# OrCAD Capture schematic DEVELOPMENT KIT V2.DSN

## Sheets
1 Diagrama de Bloques: size A4; title: Development Kit V1; Diagrama de Bloques; rev: 2.0; company: Oficina Técnica, UC3M; note: OT-2015-2706
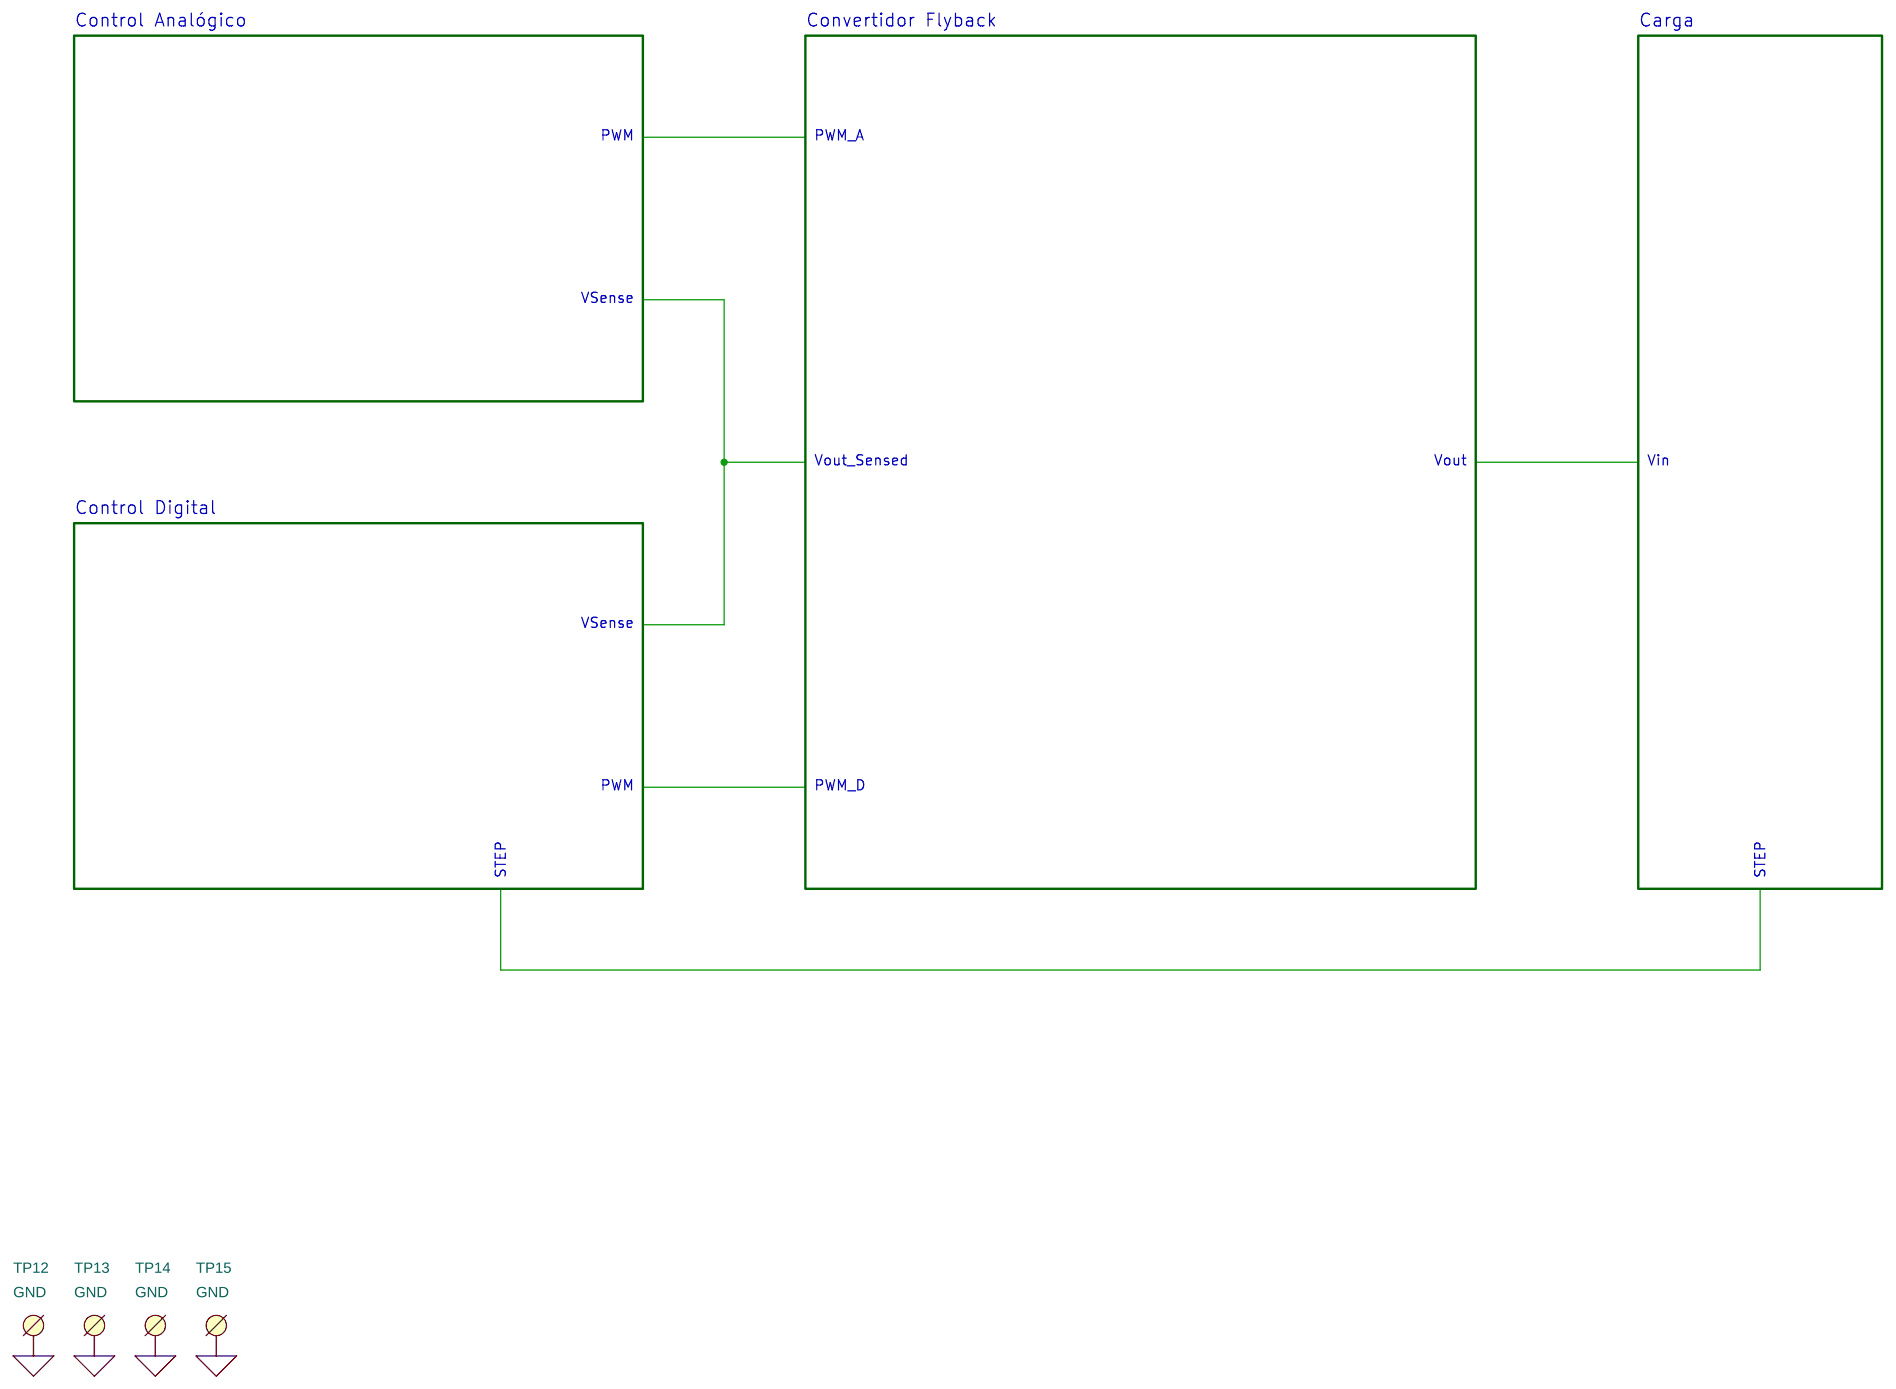
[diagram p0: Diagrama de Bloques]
2 Control Analógico: size A4; title: Development Kit V1; Control Analógico; block Control Analógico
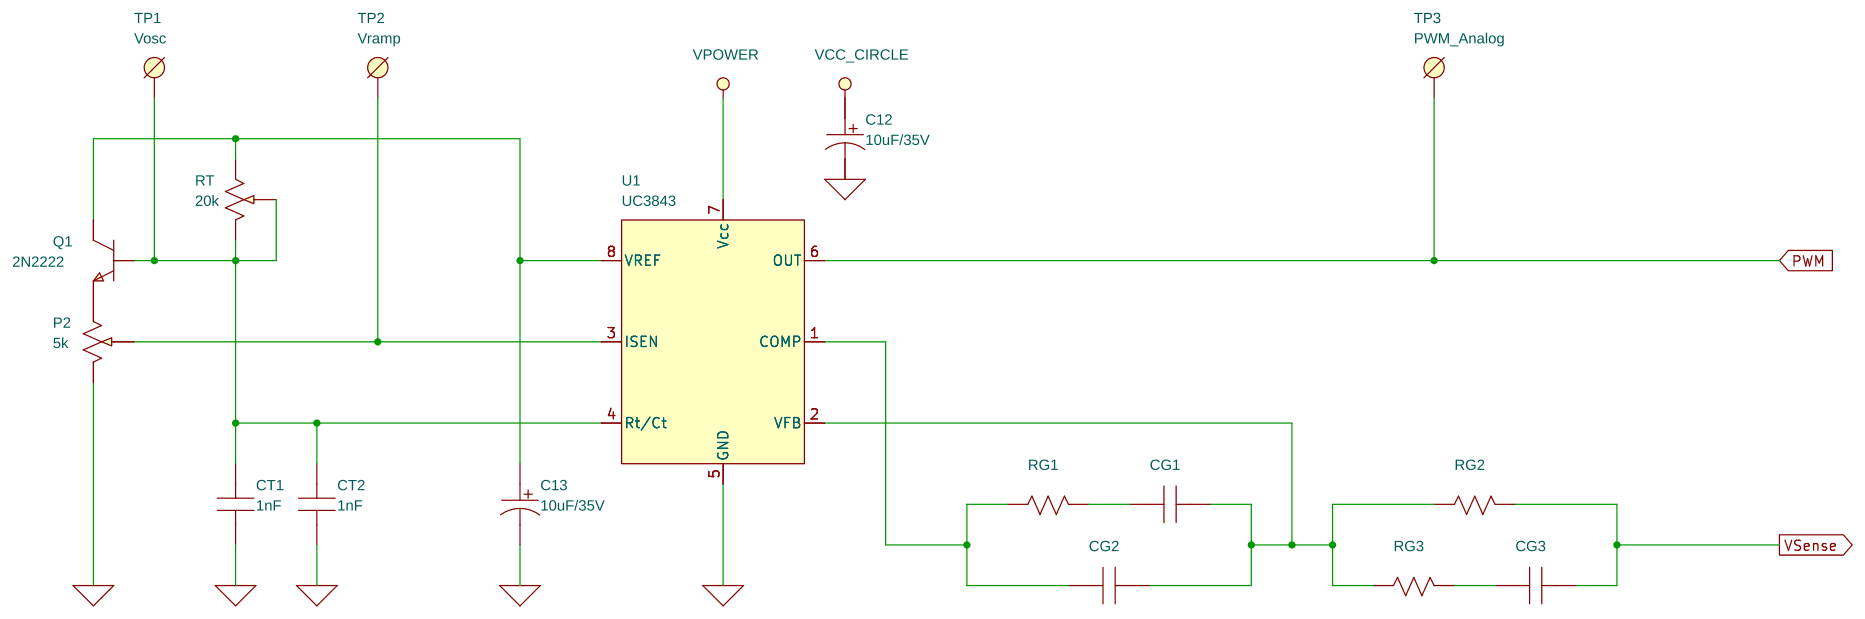
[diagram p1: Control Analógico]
3 Control Digital: size A4; title: Development Kit V1; Control Digital; block Control Digital
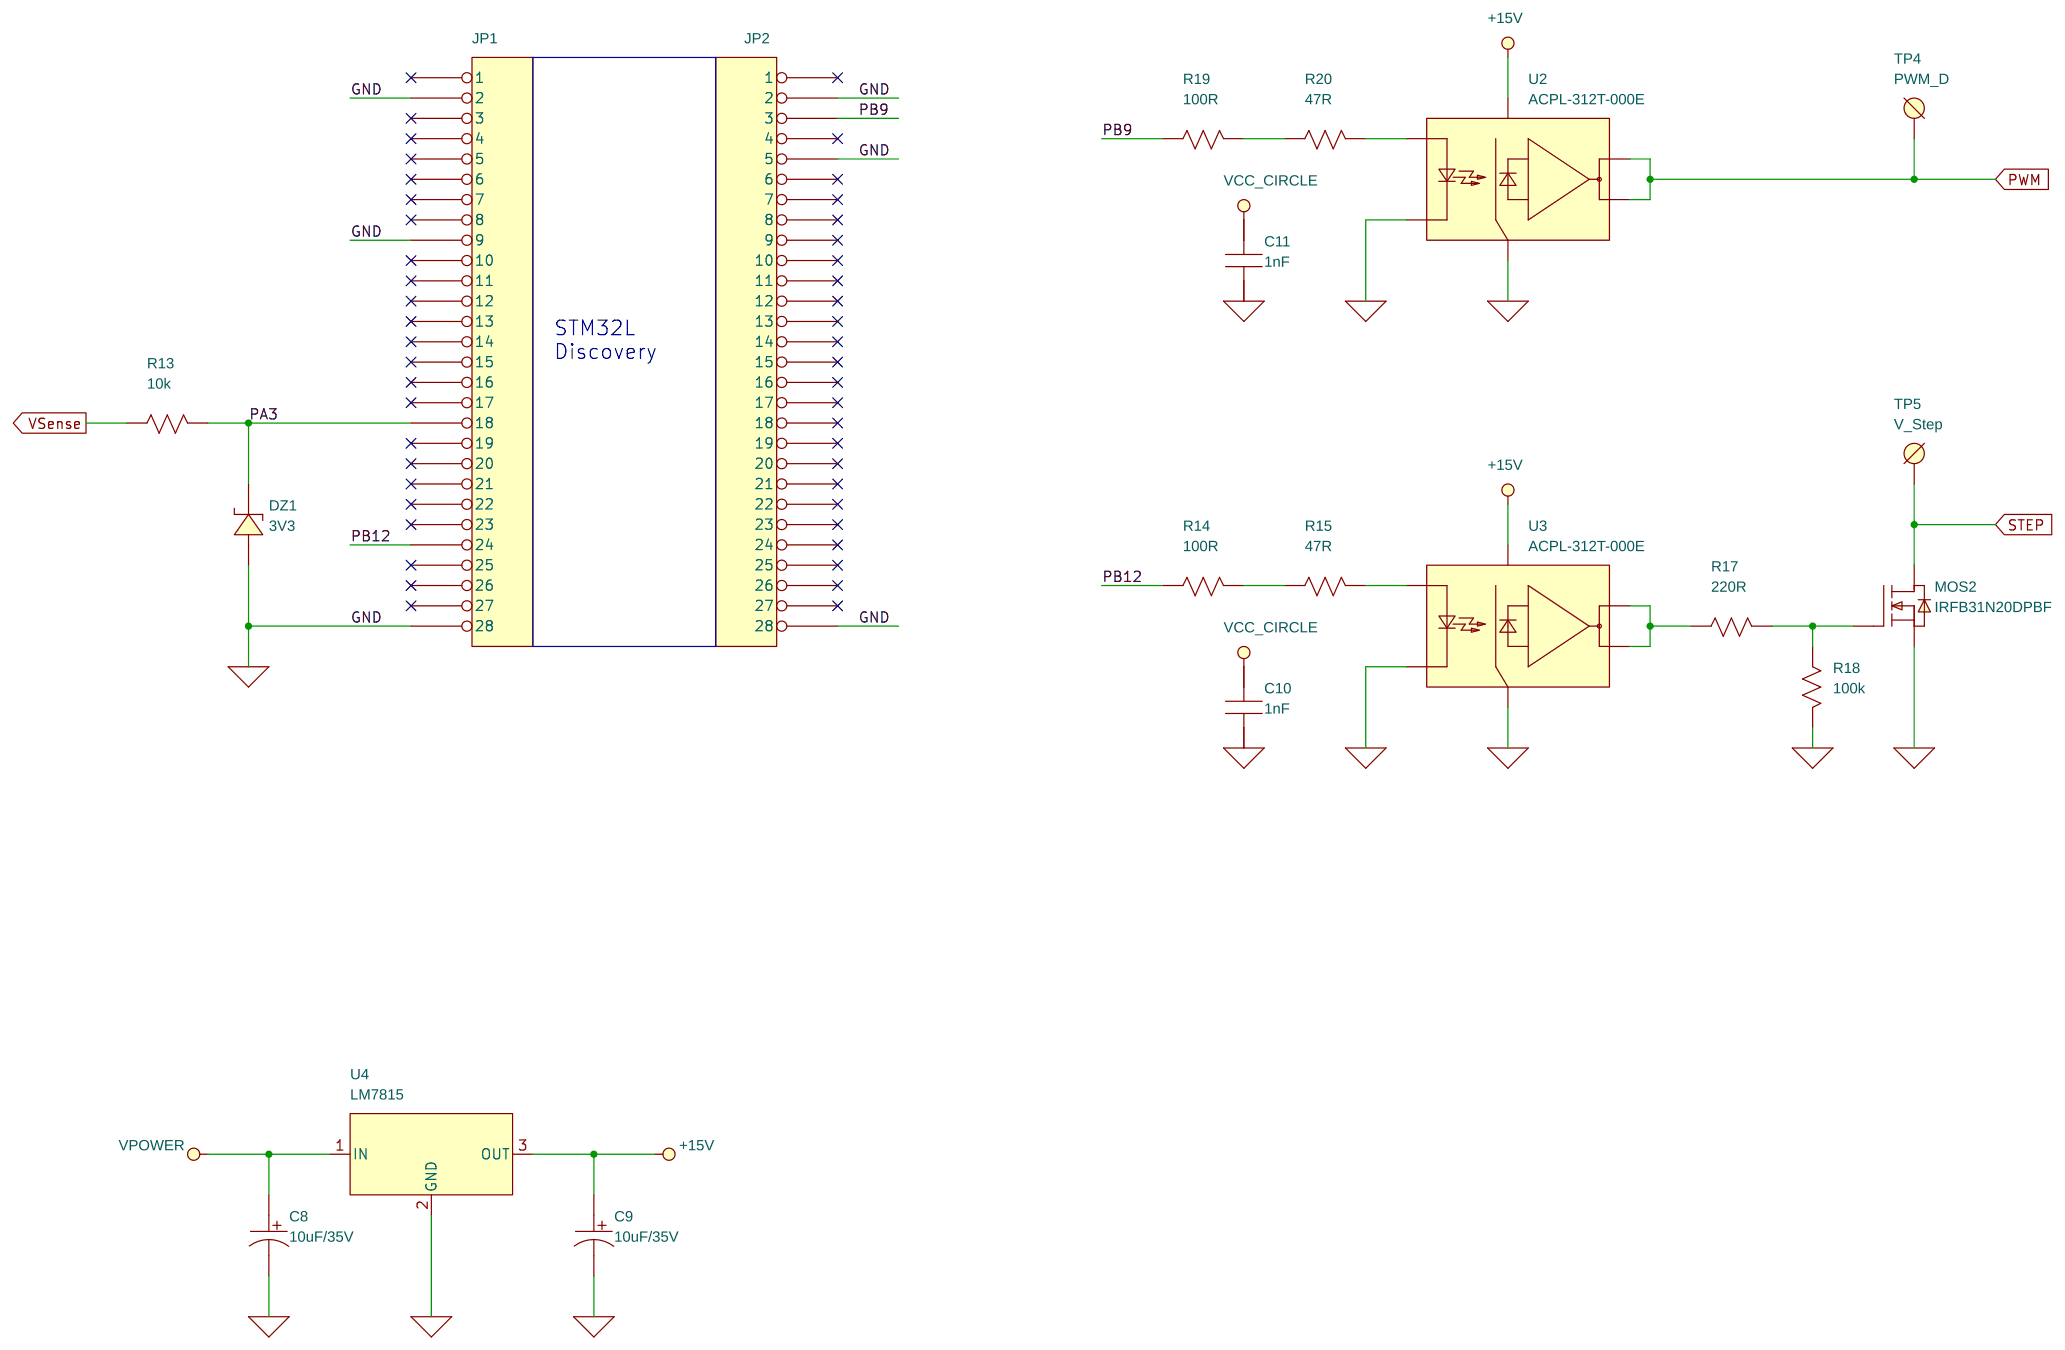
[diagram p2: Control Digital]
4 Convertidor Flyback: size A4; title: Development Kit V1; Convertidor Flyback; block Convertidor Flyback
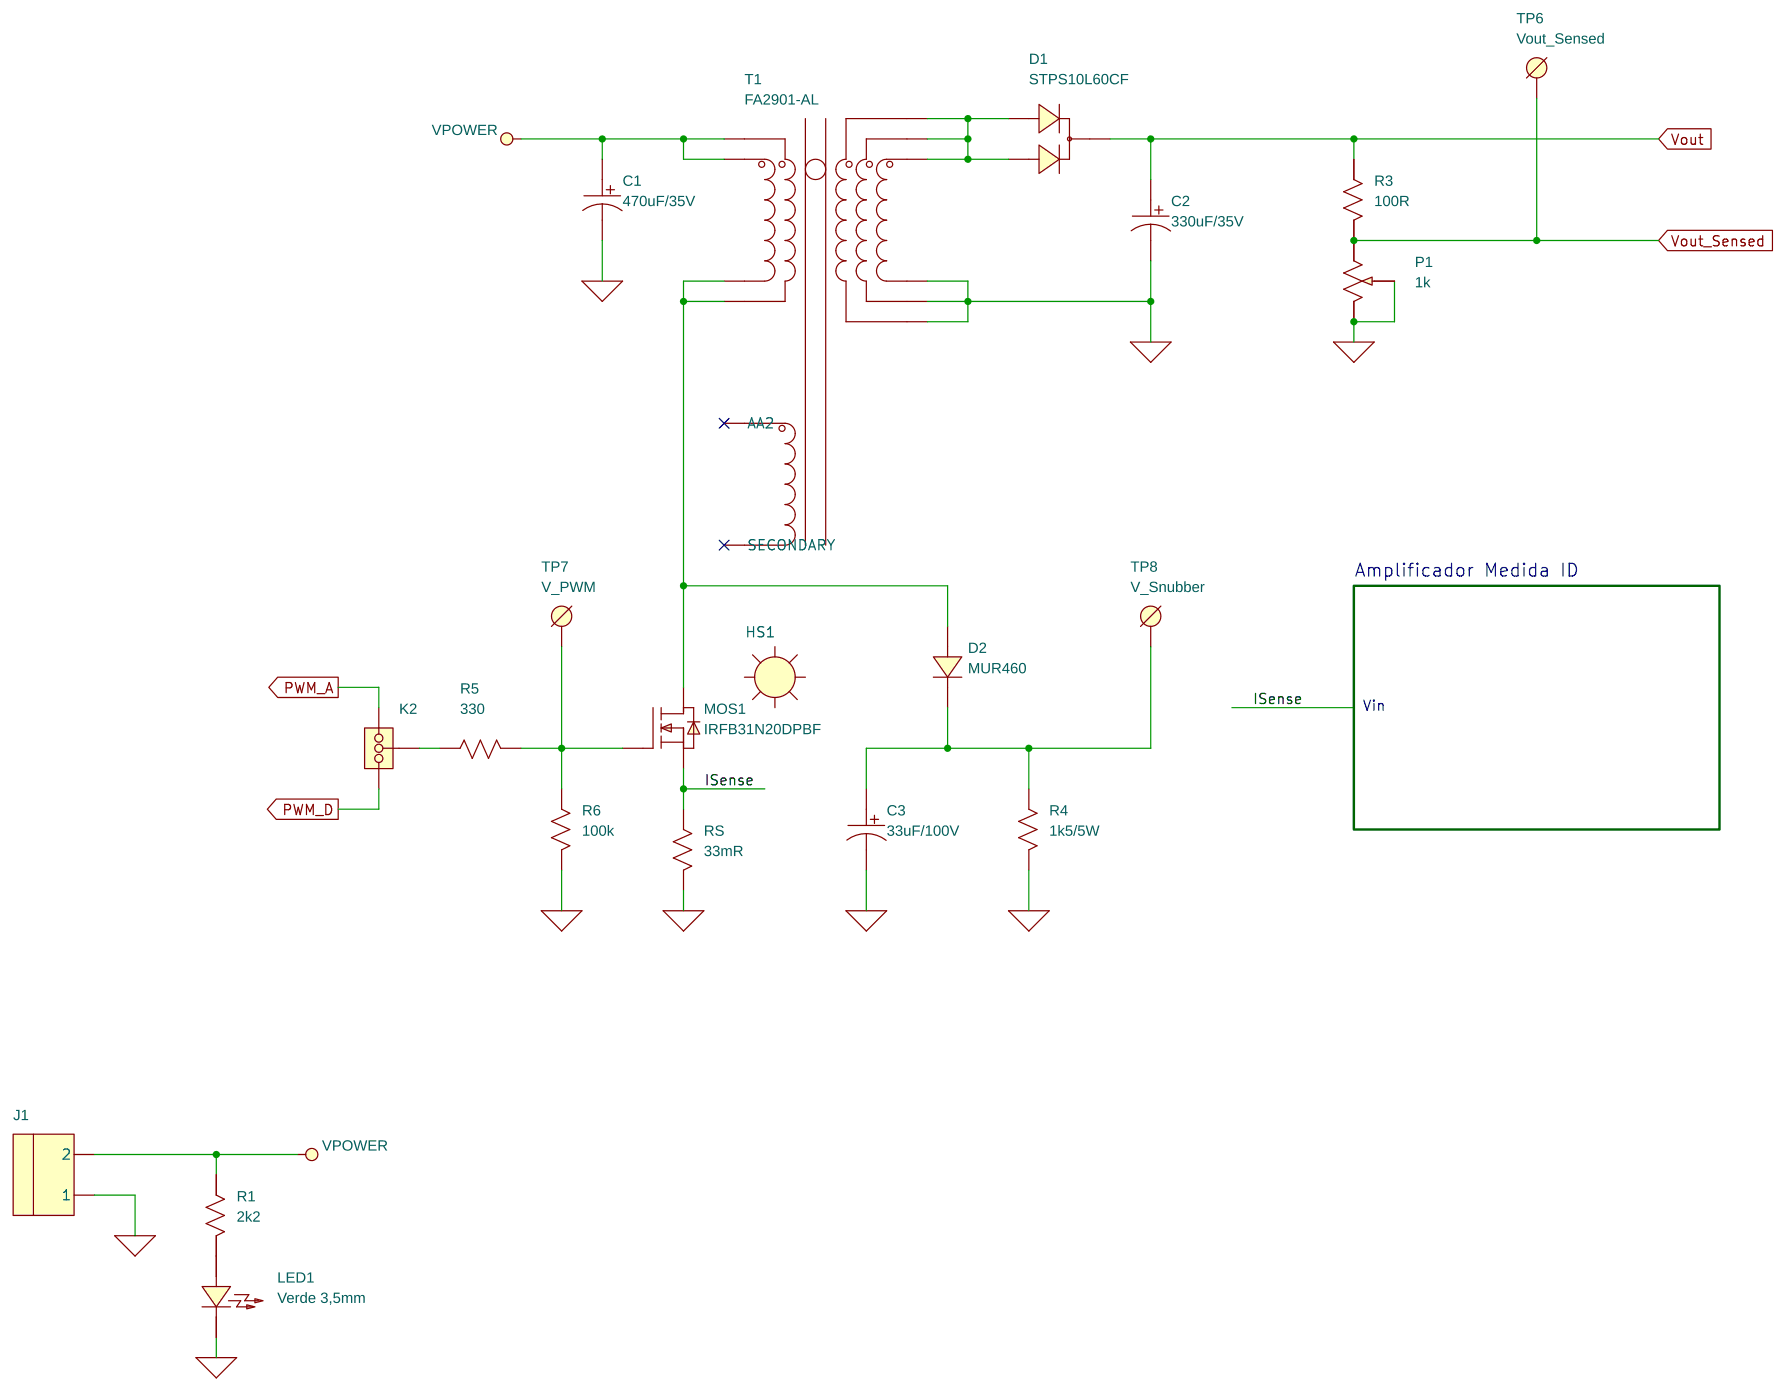
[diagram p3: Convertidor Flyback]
5 Amplificador Medida ID: size A4; title: Development Kit V1; Amplificador Medida ID; block Convertidor Flyback/Amplificador Medida ID
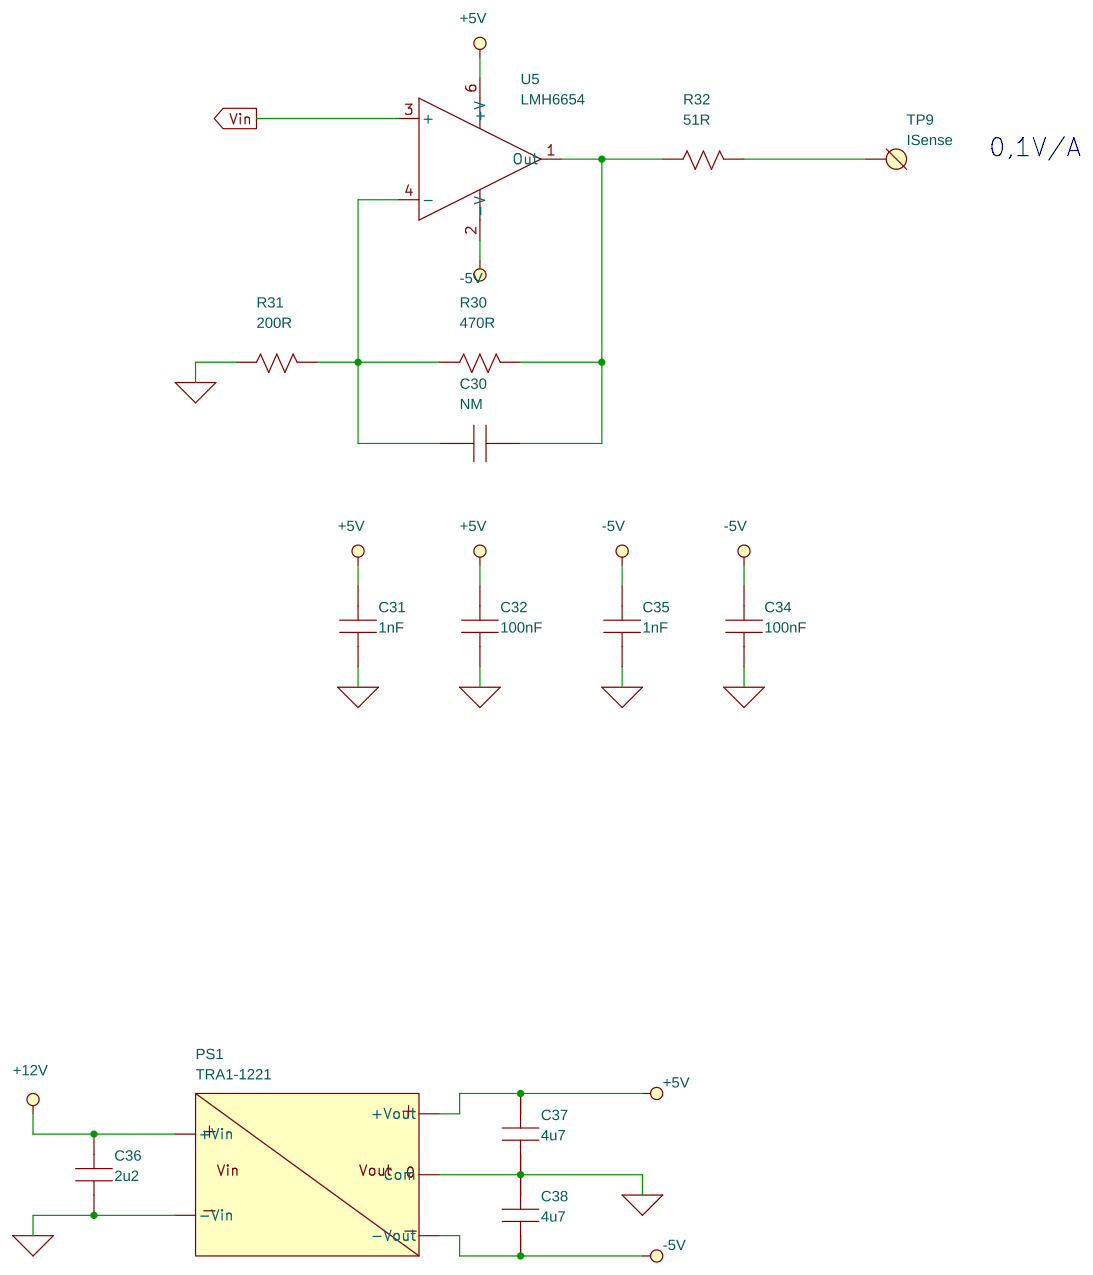
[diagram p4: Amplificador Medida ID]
6 Carga: size A4; title: Development Kit V1; Carga; block Carga
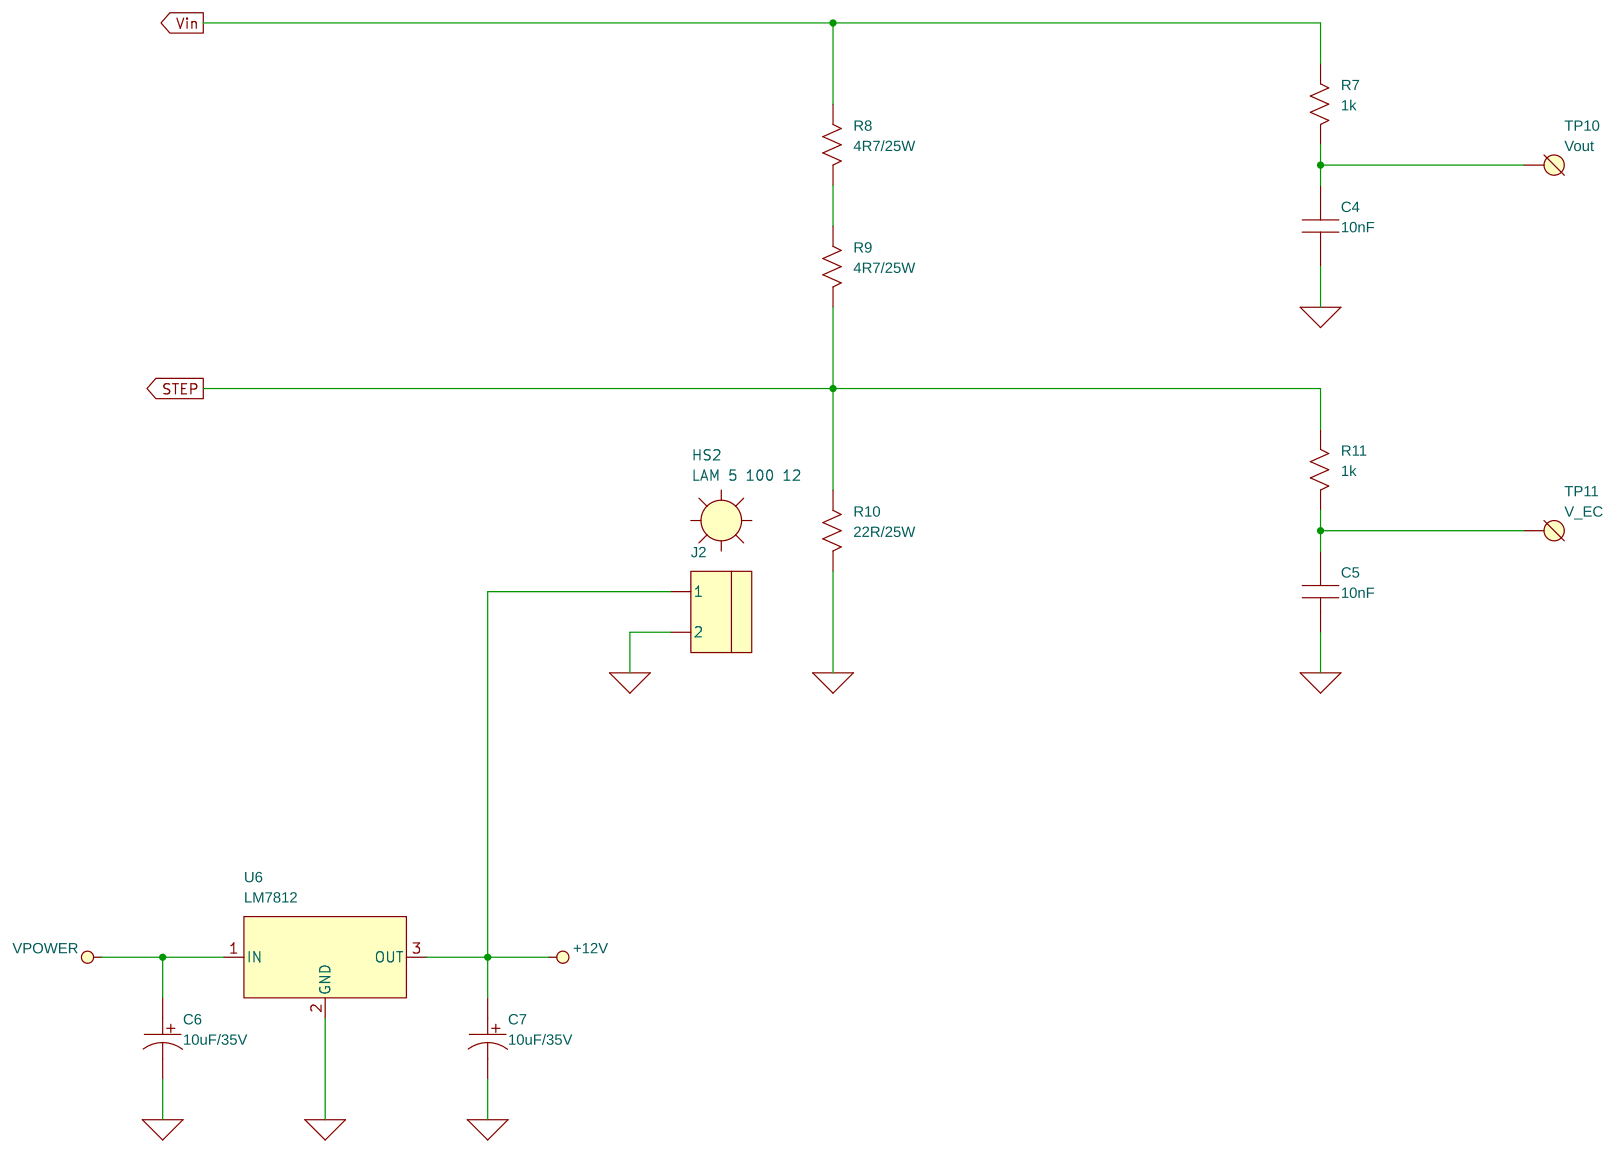
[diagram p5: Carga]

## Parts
sheet Amplificador Medida ID
C30  NM  [SM/0805]
C31  1nF  [SM/0805]
C32  100nF  [SM/1206]
C34  100nF  [SM/1206]
C35  1nF  [SM/0805]
C36  2u2  [SM/1206]
C37  4u7  [SM/1206]
C38  4u7  [SM/1206]
PS1  TRA1-1221  [SIP/DC-DC 1W/TRA1/DOBLE/.100/.076/.040]
R30  470R  [SM/0805]
R31  200R  [SM/0805]
R32  51R  [SM/0805]
TP9  ISense  [TP/.052/.150]
U5  LMH6654  [SM/SOT23/5]
sheet Carga
C4  10nF  [RAD/.300X.220/LS.200/.076/.028]
C5  10nF  [RAD/.300X.220/LS.200/.076/.028]
C6  10uF/35V  [CYL/D.200/LS.080/.064/.028]
C7  10uF/35V  [CYL/D.200/LS.080/.064/.028]
HS2  LAM 5 100 12  [DIS/50X100MM/LAM-5-100-12]
J2  MOLEX 2  [CONN/MOLEX/02/.100/.064]
R7  1k  [AX/.400X.100/.076/.028]
R8  4R7/25W  [AX/HS25/2.000X1.100/250/100]
R9  4R7/25W  [AX/HS25/2.000X1.100/250/100]
R10  22R/25W  [AX/HS25/2.000X1.100/250/100]
R11  1k  [AX/.400X.100/.076/.028]
TP10  Vout  [TP/.052/.150]
TP11  V_EC  [TP/.052/.150]
U6  LM7812  [TO220/VER/.076/.048]
sheet Control Analógico
C12  10uF/35V  [CYL/D.200/LS.080/.064/.028]
C13  10uF/35V  [CYL/D.200/LS.080/.064/.028]
CG1  CAP NP  [RAD/.300X.180/LS.200/.076/.028]
CG2  CAP NP  [RAD/.300X.180/LS.200/.076/.028]
CG3  CAP NP  [RAD/.300X.180/LS.200/.076/.028]
CT1  1nF  [RAD/.300X.180/LS.200/.076/.028]
CT2  1nF  [RAD/.300X.180/LS.200/.076/.028]
P2  5k  [VRES/.100/.400/.076/.040]
Q1  2N2222  [TO18/.052/.024]
RG1  R  [AX/.400X.100/.076/.028]
RG2  R  [AX/.400X.100/.076/.028]
RG3  R  [AX/.400X.100/.076/.028]
RT  20k  [VRES/.100/.400/.076/.040]
TP1  Vosc  [TP/.052/.150]
TP2  Vramp  [TP/.052/.150]
TP3  PWM_Analog  [TP/.052/.150]
U1  UC3843  [DIP.100/08/W.300/L.450/.064/.028]
sheet Control Digital
C8  10uF/35V  [CYL/D.200/LS.080/.064/.028]
C9  10uF/35V  [CYL/D.200/LS.080/.064/.028]
C10  1nF  [RAD/.300X.180/LS.200/.076/.028]
C11  1nF  [RAD/.300X.180/LS.200/.076/.028]
DZ1  3V3  [DAX/DO35/.076/.028]
JP1  HEADER 28  [HEADER.100/SOCKET/1X28/.064/.040]
JP2  HEADER 28  [HEADER.100/SOCKET/1X28/.064/.040]
MOS2  IRFB31N20DPBF  [TO220/VER/.076/.052]
R13  10k  [AX/.400X.100/.076/.028]
R14  100R  [AX/.400X.100/.076/.028]
R15  47R  [AX/.400X.100/.076/.028]
R17  220R  [AX/.400X.100/.076/.028]
R18  100k  [AX/.400X.100/.076/.028]
R19  100R  [AX/.400X.100/.076/.028]
R20  47R  [AX/.400X.100/.076/.028]
TP4  PWM_D  [TP/.052/.150]
TP5  V_Step  [TP/.052/.150]
U2  ACPL-312T-000E  [DIP.100/08/W.300/L.450/.064/.028]
U3  ACPL-312T-000E  [DIP.100/08/W.300/L.450/.064/.028]
U4  LM7815  [TO220/VER/.076/.048]
sheet Convertidor Flyback
C1  470uF/35V  [CYL/D.400/LS.200/.088/.036]
C2  330uF/35V  [CYL/D.400/LS.200/.088/.036]
C3  33uF/100V  [CYL/D.400/LS.200/.088/.036]
D1  STPS10L60CF  [TO220/VER/.076/.052]
D2  MUR460  [DAX/DO201/.100/.060]
HS1  HEATSINK  [TO220/DIS/VER/13X35]
J1  MOLEX 2  [PWR_JACK]
K2  JUMPER 3  [SIP.100/03/L.300/.076/.040]
LED1  Verde 3,5mm  [CYL/LED 3,5MM/LS.100/.070/.032]
MOS1  IRFB31N20DPBF  [TO220/VER/.076/.052]
P1  1k  [VRES/.100/.400/.076/.040]
R1  2k2  [AX/.400X.100/.076/.028]
R3  100R  [AX/.400X.100/.076/.028]
R4  1k5/5W  [RAD/.520X.360/LS.200/.100/.040]
R5  330  [AX/.400X.100/.076/.028]
R6  100k  [AX/.400X.100/.076/.028]
RS  33mR  [SM/2512]
T1  FA2901-AL  [FA2901-AL]
TP6  Vout_Sensed  [TP/.052/.150]
TP7  V_PWM  [TP/.052/.150]
TP8  V_Snubber  [TP/.052/.150]
sheet Diagrama de Bloques
TP12  GND  [TP/.052/.150]
TP13  GND  [TP/.052/.150]
TP14  GND  [TP/.052/.150]
TP15  GND  [TP/.052/.150]

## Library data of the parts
C4 C5 C10 C11 C30-C32 C34-C38 CG1-CG3 CT1 CT2 = CAP_NP
PS1 = DC_DC_DOBLE_TRA1_Series
R1 R3-R11 R13-R15 R17-R20 R30-R32 RG1-RG3 RS = R
TP1-TP15 = TEST_POINT
U5 = LMH6654_0
C1-C3 C6-C9 C12 C13 = CAP_POL
HS1 HS2 = HEATSINK
J1 J2 = MOLEX_2
U4 U6 = LM78xx
P1 P2 RT = POT
Q1 = BJT_NPN_0
U1 = UC3843
DZ1 = DIODE_ZENER
JP1 = HEADER_28
JP2 = HEADER_28_1
MOS1 MOS2 = MOSFET_N_ENHANCEMENT_W_DIODE_0
U2 U3 = ACPL-312T-000E
D1 = DIODE_DOUBE_CK
D2 = DIODE
K2 = JUMPER_3
LED1 = LED
T1 = TRAFO_FA2901-AL

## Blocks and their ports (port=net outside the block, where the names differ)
Control Analógico = schematic B1, on sheet Diagrama de Bloques: PWM=N00013, VSense=N00019
Control Digital = schematic B2, on sheet Diagrama de Bloques: VSense=N00019, PWM=N00016, STEP=N00188
Convertidor Flyback = schematic B3, on sheet Diagrama de Bloques: PWM_A=N00013, PWM_D=N00016, Vout_Sensed=N00019, Vout=N00100
Convertidor Flyback/Amplificador Medida ID = schematic B3B1, on sheet Convertidor Flyback: Vin=Convertidor Flyback/ISense
Carga = schematic B4, on sheet Diagrama de Bloques: Vin=N00100, STEP=N00188

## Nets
+5V: C31.1 C32.1 C37.1 PS1.6(+Vout) U5.6(+V)
+12V: C7.1 C36.1 J2.1 PS1.1(+Vin) U6.3(OUT)
+15V: C9.1 C10.1 C11.1 U2.8(Vcc) U3.8(Vcc) U4.3(OUT)
-5V: C34.1 C35.1 C38.2 PS1.4(-Vout) U5.2(-V)
GND_SIGNAL: C1.2 C2.2 C3.2 C4.2 C5.2 C6.2 C7.2 C8.2 C9.2 C10.2 C11.2 C12.2 C13.2 C31.2 C32.2 C34.2 C35.2 C36.2 C37.2 C38.1 CT1.2 CT2.2 DZ1.2(ANODE) J1.1 J2.2 JP1.2 JP1.9 JP1.28 JP2.2 JP2.5 JP2.28 LED1.1(CATHODE) MOS2.3(SOURCE) P1.2(cursor) P1.3 P2.3 PS1.2(-Vin) PS1.5(Com) R4.2 R6.2 R10.2 R18.2 R31.1 RS.2 T1.7 T1.8 T1.9 TP12.1 TP13.1 TP14.1 TP15.1 U1.5(GND) U2.3(CATHODE) U2.5(Vee) U3.3(CATHODE) U3.5(Vee) U4.2(GND) U6.2(GND)
Control Digital/PA3: DZ1.1(CATHODE) JP1.18 R13.2
Control Digital/PB9: JP2.3 R19.1
Control Digital/PB12: JP1.24 R14.1
Convertidor Flyback/ISense: MOS1.3(SOURCE) RS.1 U5.3(+)
Vpower: C1.1 C6.1 C8.1 C12.1 J1.2 R1.1 T1.1 T1.2 U1.7(Vcc) U4.1(IN) U6.1(IN)
Carga/N02272: C4.1 R7.2 TP10.1
Carga/N03040: R8.2 R9.2
Carga/N03319: C5.1 R11.2 TP11.1
Control Analógico/N00088: P2.2(cursor) TP2.1 U1.3(ISEN)
Control Analógico/N00114: CT1.1 CT2.1 Q1.2(base) RT.2(cursor) RT.3 TP1.1 U1.4(Rt/Ct)
Control Analógico/N00273: C13.1 Q1.3(COLLECTOR) RT.1 U1.8(VREF)
Control Analógico/N00672: CG3.1 RG3.2
Control Analógico/N00720: CG1.2 CG2.2 RG2.1 RG3.1 U1.2(VFB)
Control Analógico/N00842: CG1.1 RG1.2
Control Analógico/N00845: CG2.1 RG1.1 U1.1(COMP)
Control Digital/N00356: R20.2 U2.2(ANODE)
Control Digital/N00359: R19.2 R20.1
Control Digital/N00380: R14.2 R15.1
Control Digital/N00428: R17.1 U3.6(Vo) U3.7(Vo)
Control Digital/N00483: MOS2.1(GATE) R17.2 R18.1
Control Digital/N00842: R15.2 U3.2(ANODE)
Convertidor Flyback/Amplificador Medida ID/N02363: C30.1 R30.1 R31.2 U5.4(-)
Convertidor Flyback/Amplificador Medida ID/N02381: C30.2 R30.2 R32.1 U5.1(Out)
Convertidor Flyback/Amplificador Medida ID/N08431: R32.2 TP9.1
Convertidor Flyback/N00622: D1.1(ANODE) D1.3(ANODE) T1.10 T1.11 T1.12
Convertidor Flyback/N00667: D2.2(ANODE) MOS1.2(DRAIN) T1.3 T1.4
Convertidor Flyback/N02464: C3.1 D2.1(CATHODE) R4.1 TP8.1
Convertidor Flyback/N02603: MOS1.1(GATE) R5.2 R6.1 TP7.1
Convertidor Flyback/N02626: K2.2 R5.1
N00013: K2.1 TP3.1 U1.6(OUT)
N00016: K2.3 TP4.1 U2.6(Vo) U2.7(Vo)
N00019: CG3.2 P1.1 R3.2 R13.1 RG2.2 TP6.1
N00100: C2.1 D1.2(CATHODE) R3.1 R7.1 R8.1
N00188: MOS2.2(DRAIN) R9.1 R10.1 R11.1 TP5.1
N01227: P2.1 Q1.1(EMITTER)
N03681: LED1.2(ANODE) R1.2

Not connected (* = marked no-connect by the designer): JP1 1* 3* 4* 5* 6* 7* 8* 10* 11* 12* 13* 14* 15* 16* 17* 19* 20* 21* 22* 23* 25* 26* 27*; JP2 1* 4* 6* 7* 8* 9* 10* 11* 12* 13* 14* 15* 16* 17* 18* 19* 20* 21* 22* 23* 24* 25* 26* 27*; T1 5(AA2)* 6(SECONDARY)*

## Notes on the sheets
sheet 3
- STM32L
  Discovery
sheet 5
- 0,1V/A
